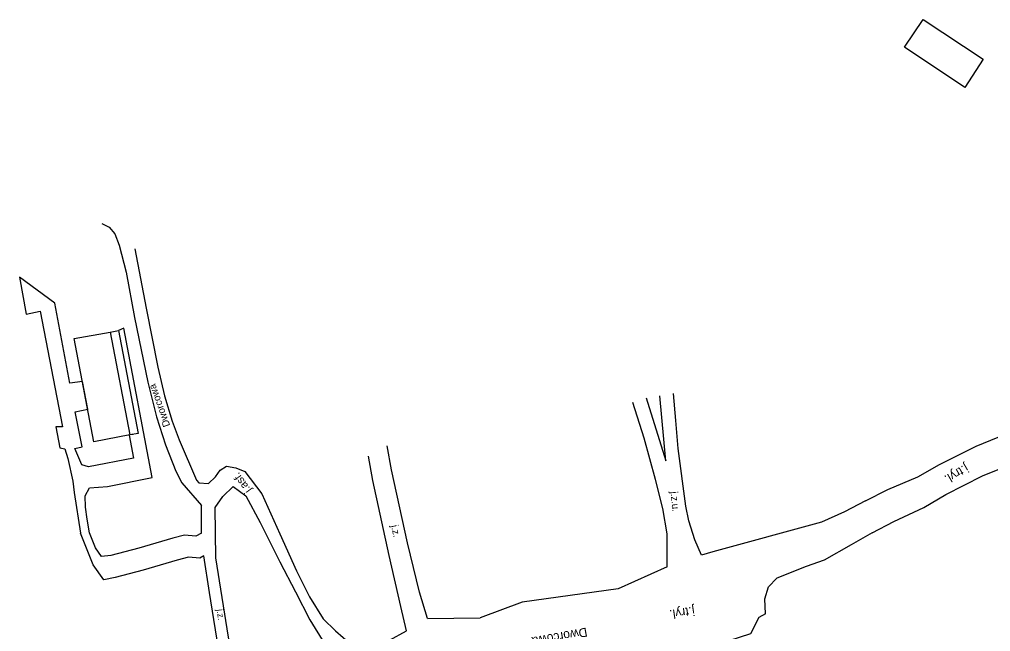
# Model space of a CAD drawing. Extents: x 6541740 to 6556805, y 5525233 to 5530361.
# Drawn here: x 6555075.5 to 6555210.5, y 5525796.3 to 5525881.4 of the extents above; entities that cross this region are included whole.
import ezdxf

# ---------------------------------------------------------------- set-up
doc = ezdxf.new("R2010")
doc.units = 0
doc.layers.add('TOR_SCH-budynki', color=7, linetype='Continuous')
doc.layers.add('TOR_SCH-przejazdy+drogi istniejace', color=7, linetype='Continuous')

msp = doc.modelspace()

# ---------------------------------------------------------------- linework, layer by layer
at = {"layer": 'TOR_SCH-budynki'}
for p, q in [((6555198.52, 5525877.57), (6555201.1, 5525881.43)), ((6555201.1, 5525881.43), (6555209.44, 5525875.91)), ((6555206.88, 5525871.98), (6555198.52, 5525877.57)), ((6555209.44, 5525875.91), (6555206.88, 5525871.98)), ((6555083.17, 5525837.05), (6555088.16, 5525837.97)), ((6555088.16, 5525837.97), (6555089.32, 5525838.19)), ((6555088.16, 5525837.97), (6555090.87, 5525823.66)), ((6555089.32, 5525838.19), (6555092.03, 5525823.87)), ((6555085.88, 5525822.73), (6555083.17, 5525837.05)), ((6555090.87, 5525823.66), (6555085.88, 5525822.73)), ((6555092.03, 5525823.87), (6555090.87, 5525823.66))]:
    msp.add_line(p, q, dxfattribs=at)
at = {"layer": 'TOR_SCH-przejazdy+drogi istniejace'}
for p, q in [((6555080.48, 5525842), (6555075.54, 5525845.59)), ((6555075.54, 5525845.59), (6555076.48, 5525840.46)), ((6555082.53, 5525830.87), (6555080.48, 5525842)), ((6555076.48, 5525840.46), (6555078.43, 5525840.85)), ((6555078.43, 5525840.85), (6555081.53, 5525824.8)), ((6555090.05, 5525838.51), (6555089.32, 5525838.19)), ((6555089.32, 5525838.19), (6555092.03, 5525823.87)), ((6555093.97, 5525817.76), (6555090.05, 5525838.51)), ((6555084.3, 5525831.09), (6555082.53, 5525830.87)), ((6555085.03, 5525827.23), (6555084.3, 5525831.09)), ((6555083.28, 5525826.9), (6555085.03, 5525827.23)), ((6555084.24, 5525822.02), (6555083.28, 5525826.9)), ((6555081.53, 5525824.8), (6555080.61, 5525824.81)), ((6555080.61, 5525824.81), (6555081.16, 5525821.86)), ((6555090.87, 5525823.66), (6555090.77, 5525823.64)), ((6555090.77, 5525823.64), (6555091.39, 5525820.45)), ((6555091.34, 5525823.75), (6555090.87, 5525823.66)), ((6555081.16, 5525821.86), (6555081.83, 5525821.73)), ((6555081.83, 5525821.73), (6555082.25, 5525820.39)), ((6555083.22, 5525821.8), (6555084.24, 5525822.02)), ((6555084.22, 5525819.52), (6555083.22, 5525821.8)), ((6555082.25, 5525820.39), (6555082.94, 5525817.22)), ((6555091.39, 5525820.45), (6555085.16, 5525819.22)), ((6555085.16, 5525819.22), (6555084.22, 5525819.52)), ((6555087.77, 5525816.52), (6555093.97, 5525817.76)), ((6555082.94, 5525817.22), (6555083.16, 5525815.66)), ((6555084.67, 5525815.18), (6555085.27, 5525816.3)), ((6555085.27, 5525816.3), (6555087.77, 5525816.52)), ((6555083.16, 5525815.66), (6555084.02, 5525810)), ((6555084.71, 5525813.62), (6555084.67, 5525815.18)), ((6555084.93, 5525811.95), (6555084.71, 5525813.62)), ((6555100.82, 5525810.01), (6555100.86, 5525813.86)), ((6555085.29, 5525810.08), (6555084.93, 5525811.95))]:
    msp.add_line(p, q, dxfattribs=at)
for points in [[(6555087, 5525853.07), (6555088.03, 5525852.57), (6555088.78, 5525851.6), (6555089.4, 5525850.03), (6555090.35, 5525846.31), (6555091.51, 5525840), (6555093.37, 5525831), (6555094.57, 5525826.19), (6555095.83, 5525822.3), (6555097.29, 5525818.63), (6555098.1, 5525817.02)], [(6555091.56, 5525849.53), (6555093.16, 5525841.27), (6555094.79, 5525833.07), (6555095.72, 5525829.11), (6555096.76, 5525825.57), (6555097.74, 5525822.99), (6555097.74, 5525822.99), (6555100.12, 5525817.38)], [(6555204.25, 5525815.4), (6555209.33, 5525817.96), (6555214.41, 5525820.04), (6555219.12, 5525822.16), (6555224.09, 5525824.77), (6555225.71, 5525826.86), (6555226.81, 5525829.89), (6555227.94, 5525837.73), (6555228.4, 5525842.13)], [(6555170.28, 5525806.96), (6555169.36, 5525809.07), (6555168.56, 5525811.73), (6555168.11, 5525813.78), (6555167.06, 5525821.77), (6555166.73, 5525825.69), (6555166.42, 5525829.45)], [(6555165.55, 5525805.34), (6555165.51, 5525809.9), (6555164.92, 5525813.42), (6555163.91, 5525817.46), (6555162.32, 5525823.24), (6555160.78, 5525828.18)], [(6555162.6, 5525828.84), (6555165.33, 5525820.08), (6555164.51, 5525829.12)], [(6555203.38, 5525819.56), (6555208.47, 5525822.12), (6555213.56, 5525824.21), (6555218.26, 5525826.32), (6555222.33, 5525829.16), (6555222.33, 5525829.16)], [(6555132.22, 5525798.14), (6555131.13, 5525801.79), (6555129.44, 5525808.65), (6555127.25, 5525818.83), (6555126.64, 5525822.14)], [(6555129.31, 5525796.42), (6555128.54, 5525799.81), (6555126.89, 5525806.92), (6555124.64, 5525817.35), (6555124.03, 5525820.73)], [(6555102.76, 5525817.86), (6555103.41, 5525818.76), (6555104.29, 5525819.32), (6555105.62, 5525819.09), (6555106.87, 5525818.59)], [(6555193.1, 5525814.49), (6555196.18, 5525816.07), (6555200.35, 5525817.85), (6555203.38, 5525819.56)], [(6555100.12, 5525817.38), (6555100.46, 5525817.01), (6555101.8, 5525816.9), (6555102.76, 5525817.86)], [(6555106.87, 5525818.59), (6555109.22, 5525815.47), (6555111.71, 5525809.92), (6555114.03, 5525804.77), (6555115.86, 5525801.16), (6555117.76, 5525798.12), (6555119.44, 5525796.45)], [(6555098.1, 5525817.02), (6555100.86, 5525813.86)], [(6555103.82, 5525815.1), (6555105.24, 5525816.49), (6555106.98, 5525815.22), (6555108.97, 5525811.49), (6555111.71, 5525806.01), (6555113.9, 5525801.86), (6555115.87, 5525797.97), (6555117.99, 5525794.58), (6555119.79, 5525792.78)], [(6555102.75, 5525813.58), (6555103.82, 5525815.1)], [(6555194.02, 5525810.07), (6555197, 5525811.65), (6555201.17, 5525813.6), (6555204.25, 5525815.4)], [(6555107.2, 5525779.15), (6555106.47, 5525784.86), (6555104.58, 5525795.56), (6555102.84, 5525806.59), (6555102.75, 5525813.58)], [(6555193.1, 5525814.49), (6555190.16, 5525812.99), (6555186.96, 5525811.53), (6555171.86, 5525807.44), (6555170.28, 5525806.96)], [(6555101.17, 5525806.84), (6555101.17, 5525806.84), (6555100.61, 5525806.55), (6555099.03, 5525806.66), (6555097.44, 5525806.25), (6555092.73, 5525804.89), (6555088.83, 5525803.87), (6555087.28, 5525803.53), (6555085.79, 5525805.61), (6555084.02, 5525810)], [(6555100.82, 5525810.01), (6555100.82, 5525810.01), (6555100.03, 5525809.61), (6555098.47, 5525809.72), (6555096.84, 5525809.3), (6555092.14, 5525807.94), (6555088.25, 5525806.92), (6555086.94, 5525806.79), (6555086.09, 5525807.99), (6555085.29, 5525810.08)], [(6555194.02, 5525810.07), (6555191.09, 5525808.41), (6555187.33, 5525806.25), (6555184.83, 5525805.36), (6555180.79, 5525803.78), (6555179.61, 5525802.56)], [(6555105.55, 5525779.33), (6555104.85, 5525784.85), (6555102.97, 5525795.43), (6555101.97, 5525801.78), (6555101.17, 5525806.84), (6555101.17, 5525806.84)], [(6555165.55, 5525805.34), (6555165.55, 5525805.34), (6555158.74, 5525802.27), (6555145.38, 5525800.44), (6555139.57, 5525798.23)], [(6555179.19, 5525798.81), (6555179.08, 5525800.88), (6555179.61, 5525802.56)], [(6555179.19, 5525798.81), (6555178.27, 5525798.27), (6555177.11, 5525796.01), (6555174.11, 5525795.03), (6555168.85, 5525794.24), (6555160.68, 5525792.4), (6555147.29, 5525790.56), (6555140.81, 5525789.16)], [(6555132.22, 5525798.14), (6555139.57, 5525798.23)], [(6555119.44, 5525796.45), (6555121.59, 5525794.59), (6555123.69, 5525793.33), (6555125.15, 5525793.11), (6555126.95, 5525795.15), (6555129.31, 5525796.42)]]:
    msp.add_lwpolyline(points, dxfattribs=at)

# ---------------------------------------------------------------- texts
for s, height, rotation, p in [('Dworcowa', 1, 109.7537, (6555096.5, 5525824.98)), ('j.tryl.', 1.245, 210.3775, (6555206.95, 5525819.68)), ('j.asf.', 1.111, 125.7268, (6555107.81, 5525816.03)), ('j.z.u.', 1, 275.1741, (6555166.01, 5525815.77)), ('j.z.', 1, 282.1269, (6555127.17, 5525811.05)), ('j.tryl.', 1.25, 188.5254, (6555169.26, 5525799.83)), ('j.z.', 0.9, 278.9891, (6555102.93, 5525799.39)), ('Dworcowa', 1.25, 190.2125, (6555154.31, 5525796.9))]:
    msp.add_text(s, height=height, rotation=rotation, dxfattribs=at).set_placement(p)

doc.saveas('drawing.dxf')
